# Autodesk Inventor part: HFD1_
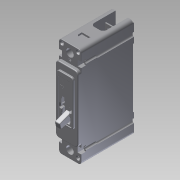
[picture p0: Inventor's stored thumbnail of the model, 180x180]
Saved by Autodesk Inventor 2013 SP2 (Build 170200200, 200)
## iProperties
Created: 2014-08
Part Number: HFD1_
Material: Generic
Document SubType Name: Modeling
Designer: DM/JS
Density: 1 g/cm^3
Description: TYPE HFD THERMAL MAGNETIC CIRCUIT BREAKERS SINGLE POLE, SERIES C
Translation Standard: STEP AP214IS
FileName: Y:\ECO-062745\WIP\New\FD1_.stp
PreProcessor: Autodesk Inventor 2012
PostProcessor: Build: 219, Release: 2012 SP2 - Date: Fri 04/27/2012
Sent Units: inch
Uncertainty: 0.00039370078740199997
MXEDIT: false
MXINVTNRV: INV Versioned Component|HFD1_|003.0
Author: DM/JS
Revision Number: 003
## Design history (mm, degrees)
node "HFD1_"
node "L1"
node "L2"
body "Solid1"
node "Base1"
